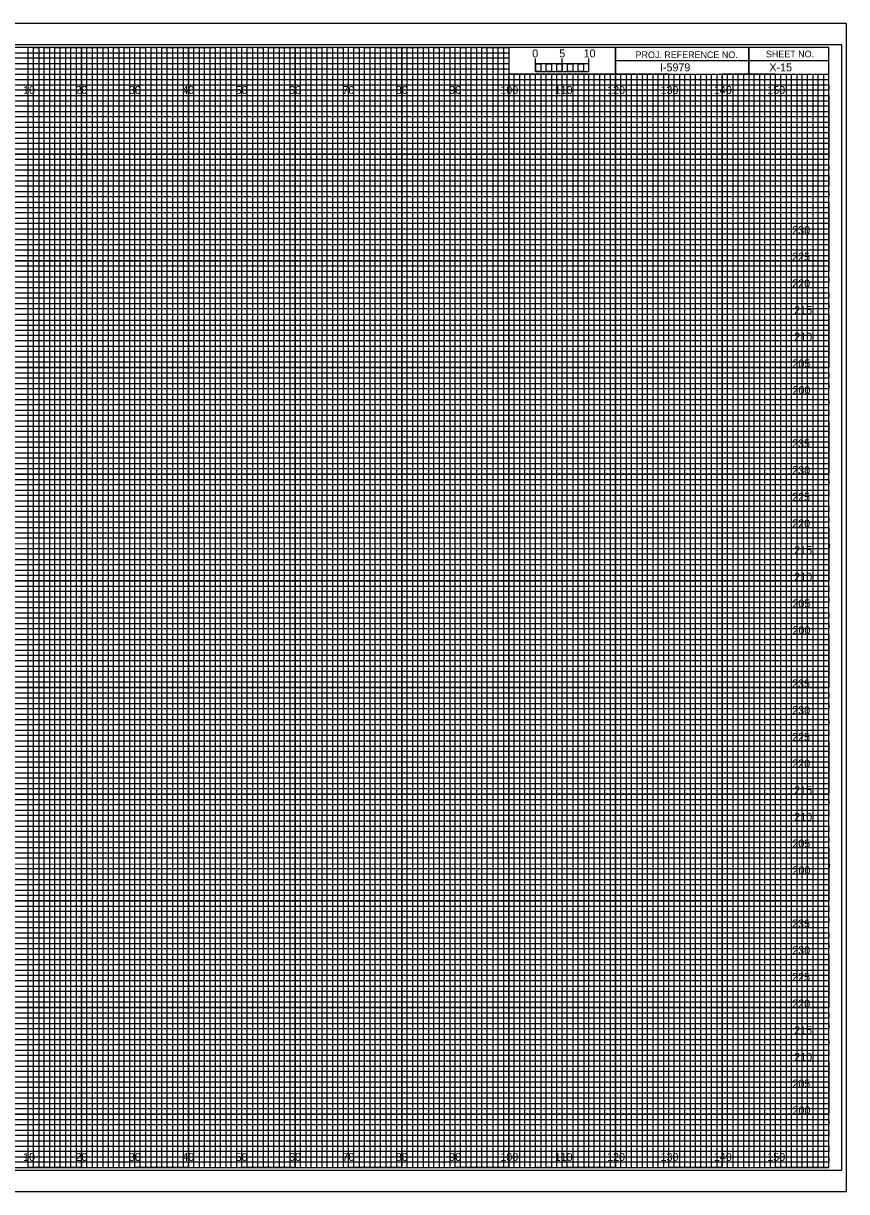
# Model space of a CAD drawing. Extents: x -13 to 323, y -5 to 654.
# Drawn here: x 169.1 to 323.3, y 215.5 to 434.5 of the extents above; entities that cross this region are included whole.
import ezdxf

# ---------------------------------------------------------------- set-up
doc = ezdxf.new("R2010")
doc.units = 0
for name, color, linetype in [('Prop XS Bar Scale Labels', 7, 'Continuous'), ('Prop XS Elevation Labels', 7, 'Continuous'), ('Prop XS Offset Labels', 7, 'Continuous'), ('Prop XS Project Number', 7, 'Continuous'), ('Prop XS Sheet Number', 7, 'Continuous'), ('Sheet Cross Section CELL', 7, 'Continuous'), ('Sheet Cross Section Grid Major CELL', 7, 'Continuous'), ('Sheet Cross Section Grid Middle CELL', 7, 'Continuous'), ('Sheet Cross Section Grid Minor 1 CELL', 7, 'Continuous'), ('Sheet Cross Section Grid Minor 2 CELL', 7, 'Continuous'), ('Sheet Cross Section Scale CELL', 7, 'Continuous'), ('Sheet Cutting Line CELL', 7, 'Continuous'), ('Sheet DOT Grid CELL', 7, 'Continuous'), ('Sheet Plot Border Inside CELL', 7, 'Continuous'), ('Sheet Plot Border Outside CELL', 7, 'Continuous')]:
    doc.layers.add(name, color=color, linetype=linetype)

msp = doc.modelspace()

# ---------------------------------------------------------------- linework, layer by layer
at = {"layer": 'Sheet Cross Section CELL'}
for p, q in [((305, 430), (305, 425)), ((305, 425), (305, 430)), ((280, 427.5), (280, 425)), ((320, 427.49), (280, 427.49)), ((280, 425), (320, 425))]:
    msp.add_line(p, q, dxfattribs=at)
for points in [[(320, 430), (0, 430), (0, 220), (320, 220)], [(280, 430), (260, 430), (260, 425.03), (280, 425.03)], [(320, 430), (280, 430), (280, 425), (320, 425)]]:
    msp.add_lwpolyline(points, close=True, dxfattribs=at)
at = {"layer": 'Sheet Cross Section Grid Major CELL'}
for p, q in [((170, 430), (160, 430)), ((170, 220), (170, 430)), ((190, 430), (180, 430)), ((180, 430), (180, 220)), ((190, 220), (190, 430)), ((210, 430), (200, 430)), ((200, 430), (200, 220)), ((210, 220), (210, 430)), ((230, 430), (220, 430)), ((220, 430), (220, 220)), ((230, 220), (230, 430)), ((250, 430), (240, 430)), ((240, 430), (240, 220)), ((250, 220), (250, 430)), ((260, 430), (260, 220)), ((270, 220), (270, 425)), ((290, 425), (280, 425)), ((280, 425), (280, 220)), ((290, 220), (290, 425)), ((310, 425), (300, 425)), ((300, 425), (300, 220)), ((310, 220), (310, 425)), ((180, 220), (170, 220)), ((200, 220), (190, 220)), ((220, 220), (210, 220)), ((240, 220), (230, 220)), ((260, 220), (250, 220)), ((280, 220), (270, 220)), ((300, 220), (290, 220)), ((320, 220), (310, 220)), ((320, 220), (320, 220))]:
    msp.add_line(p, q, dxfattribs=at)
for points in [[(0, 420), (320, 420), (320, 410), (0, 410)], [(0, 400), (320, 400), (320, 390), (0, 390)], [(0, 380), (320, 380), (320, 370), (0, 370)], [(0, 360), (320, 360), (320, 350), (0, 350)], [(0, 340), (320, 340), (320, 330), (0, 330)], [(0, 320), (320, 320), (320, 310), (0, 310)], [(0, 300), (320, 300), (320, 290), (0, 290)], [(0, 280), (320, 280), (320, 270), (0, 270)], [(0, 260), (320, 260), (320, 250), (0, 250)], [(0, 240), (320, 240), (320, 230), (0, 230)]]:
    msp.add_lwpolyline(points, dxfattribs=at)
at = {"layer": 'Sheet Cross Section Grid Middle CELL'}
for points in [[(165, 220), (175, 220), (175, 430), (185, 430), (185, 220), (195, 220), (195, 430), (205, 430), (205, 220), (215, 220), (215, 430), (225, 430), (225, 220), (235, 220), (235, 430), (245, 430), (245, 220), (255, 220), (255, 430), (259.93, 430), (260, 430), (260, 425), (264.99, 425), (264.99, 220), (275, 220), (275, 425), (285, 425), (285, 220), (295, 220), (295, 425), (305, 425), (305, 220), (315, 220), (315, 425)], [(0, 425), (275, 425)], [(0, 405), (320, 405), (320, 415), (0, 415)], [(0, 385), (320, 385), (320, 395), (0, 395)], [(0, 365), (320, 365), (320, 375), (0, 375)], [(0, 345), (320, 345), (320, 355), (0, 355)], [(0, 325), (320, 325), (320, 335), (0, 335)], [(0, 305), (320, 305), (320, 315), (0, 315)], [(0, 285), (320, 285), (320, 295), (0, 295)], [(0, 265), (320, 265), (320, 275), (0, 275)], [(0, 245), (320, 245), (320, 255), (0, 255)], [(0, 225), (320, 225), (320, 235), (0, 235)]]:
    msp.add_lwpolyline(points, dxfattribs=at)
at = {"layer": 'Sheet Cross Section Grid Minor 1 CELL'}
for p, q in [((0, 429), (260, 429)), ((260, 427.98), (0, 427.98)), ((260, 429), (260, 427.98)), ((0, 427), (260, 427)), ((260, 425.89), (0, 425.89)), ((260, 427), (260, 425.89)), ((0, 424), (320, 424))]:
    msp.add_line(p, q, dxfattribs=at)
for points in [[(0, 423), (270, 423), (320, 423), (320, 422), (0, 422)], [(0, 421), (320, 421), (320, 419), (0, 419)], [(0, 418), (320, 418), (320, 417), (0, 416.98)], [(0, 416), (320, 416), (320, 414), (0, 414)], [(0, 413), (320, 413), (320, 412), (0, 412)], [(0, 411), (320, 411), (320, 409), (0, 409)], [(0, 408), (320, 408), (320, 407), (0, 407)], [(0, 406), (320, 406), (320, 404), (0, 404)], [(0, 403), (320, 403), (320, 402), (0, 402)], [(0, 401), (320, 401), (320, 399), (0, 399)], [(0, 398), (320, 398), (320, 397), (0, 397)], [(0, 396), (320, 396), (320, 393.95), (320, 393), (320, 392), (0, 392)], [(0, 394), (320, 394), (320, 393), (0, 393)], [(0, 391), (320, 391), (320, 389), (0, 389.03)], [(0, 389.03), (320, 389), (320, 388), (0, 388)], [(0, 387), (320, 387), (320, 386), (0, 386)], [(0, 384), (320, 384), (320, 383), (0, 383)], [(0, 382), (320, 382), (320, 381), (0, 381)], [(-0.07, 378.89), (320, 378.89), (320, 377.88), (-0.07, 377.88)], [(0, 377), (320, 377), (320, 376), (0, 376)], [(0, 374), (320, 374), (320, 373), (0, 373)], [(0, 372), (320, 372), (320, 371), (0, 371)], [(0, 369), (320, 369), (320, 368), (0, 368)], [(0, 367), (320, 367), (320, 366), (0, 366)], [(0, 364), (320, 364), (320, 363), (0, 363)], [(0, 362), (320, 362), (320, 361), (0, 361)], [(0, 359), (320, 359), (319.99, 357.98), (0, 358)], [(0, 357), (320, 357), (320, 356), (0, 356)], [(0, 354), (320, 354), (320, 353), (0, 353)], [(0, 352), (320, 352), (320, 351), (0, 351)], [(0, 349), (320, 349), (320, 348), (0, 348)], [(0, 347), (320, 347), (320, 346), (0, 346)], [(0, 344), (320, 344), (320, 343), (0, 343)], [(0, 342), (320, 342), (320, 341), (0, 341)], [(0, 339), (320, 339), (320, 338), (0, 338)], [(0, 336.99), (320.07, 336.91), (320, 336), (0, 336)], [(0, 334), (320, 334), (320, 333), (0, 333)], [(0, 332), (320, 332), (320, 331), (0, 331)], [(0, 329), (320, 329), (320, 328), (0, 328)], [(0, 327), (320, 327), (320, 326), (0, 326)], [(0, 324), (320, 324), (320, 323), (0, 323)], [(0, 322), (320, 322), (320, 321), (0, 321)], [(0, 319), (320, 319), (320, 318), (0, 318)], [(0, 317), (320, 317), (320, 316), (0, 316)], [(0, 314), (320, 314), (320, 313), (0, 313)], [(0, 312), (320, 312), (320, 311), (0, 311)], [(0, 309), (320, 309), (320, 308), (0, 308)], [(0, 307), (320, 307), (320, 306), (0, 306)], [(0, 304), (320, 304), (320, 303), (0, 303)], [(0, 302), (320, 302), (320, 301), (0, 301)], [(0, 299), (320, 299), (319.99, 297.98), (0, 298)], [(0, 297), (320, 297), (320, 296), (0, 296)], [(0, 294), (320, 294), (320, 293), (0, 293)], [(0, 292), (320, 292), (320, 291), (0, 291)], [(0, 289), (320, 289), (320, 288), (0, 288)], [(0, 287), (320, 287), (320, 286), (0, 286)], [(0, 284), (320, 284), (320, 283), (0, 283)], [(0, 282), (320, 282), (320, 281), (0, 281)], [(0, 279), (320, 279), (320, 278), (0, 278)], [(0, 276.99), (320.07, 276.91), (320, 276), (0, 276)], [(0, 274), (320, 274), (320, 273), (0, 273)], [(0, 272), (320, 272), (320, 271), (0, 271)], [(0, 269), (320, 269), (320, 268), (0, 268)], [(0, 267), (320, 267), (320, 266), (0, 266)], [(0, 264), (320, 264), (320, 263), (0, 263)], [(0, 262), (320, 262), (320, 261), (0, 261)], [(0, 259), (320, 259), (320, 258), (0, 258)], [(0, 257), (320, 257), (320, 256), (0, 256)], [(0, 254), (320, 254), (320, 253), (0, 253)], [(0, 252), (320, 252), (320, 251), (0, 251)], [(0, 249), (320, 249), (320, 248), (0, 248)], [(0, 247), (320, 247), (320, 246), (0, 246)], [(0, 244), (320, 244), (320, 243), (0, 243)], [(0, 242), (320, 242), (320, 241), (0, 241)], [(0, 239), (320, 239), (320, 238), (0, 238)], [(0, 237), (320, 237), (320, 236), (0, 236)], [(0, 234), (320, 234), (320, 233), (0, 233)], [(0, 232), (320, 232), (320, 231), (0, 231)], [(0, 229), (320, 229), (320, 228), (0, 228)], [(0, 227), (320, 227), (320, 226), (0, 226)], [(0, 224), (320, 224), (320, 223), (0, 223)], [(0, 222), (320, 222), (320, 221), (0, 221)]]:
    msp.add_lwpolyline(points, dxfattribs=at)
at = {"layer": 'Sheet Cross Section Grid Minor 2 CELL'}
for p, q in [((267, 425), (266.01, 425)), ((266.01, 425), (266.01, 220)), ((267, 220), (267, 425)), ((269, 425), (268, 425)), ((268, 425), (268, 220)), ((269, 220), (269, 425)), ((266.01, 220), (265, 220)), ((268, 220), (267, 220))]:
    msp.add_line(p, q, dxfattribs=at)
for points in [[(170, 220), (171, 220), (171, 430), (172, 430), (172, 220)], [(172, 220), (173, 220), (173, 430), (174, 430), (174, 220)], [(175, 220), (176, 220), (176, 430), (177, 430), (177, 220)], [(177, 220), (178, 220), (178, 430), (179, 430), (179, 220)], [(180, 220), (181, 220), (181, 430), (182, 430), (182, 220)], [(182, 220), (183, 220), (183, 430), (184, 430), (184, 220)], [(185, 220), (186, 220), (186, 430), (187, 430), (187, 220)], [(187, 220), (188, 220), (188, 430), (189, 430), (189, 220)], [(190, 220), (191, 220), (191, 430), (192, 430), (192, 220)], [(192, 220), (193, 220), (193, 430), (194, 430), (194, 220)], [(195, 220), (196, 220), (196, 430), (197, 430), (197, 220)], [(197, 220), (198, 220), (198, 430), (199, 430), (199, 220)], [(200, 220), (201, 220), (201, 430), (202, 430), (202, 220)], [(202, 220), (203, 220), (203, 430), (204, 430), (204, 220)], [(205, 220), (206, 220), (206, 430), (207, 430), (207, 220)], [(207, 220), (208, 220), (208, 430), (209, 430), (209, 220)], [(210, 220), (211, 220), (211, 430), (212, 430), (212, 220)], [(212, 220), (213, 220), (213, 430), (214, 430), (214, 220)], [(215, 220), (216, 220), (216, 430), (217, 430), (217, 220)], [(217, 220), (218, 220), (218, 430), (219, 430), (219, 220)], [(220, 220), (221, 220), (221, 430), (222, 430), (222, 220)], [(222, 220), (223, 220), (223, 430), (224, 430), (224, 220)], [(225, 220), (226, 220), (226, 430), (227, 430), (227, 220)], [(227, 220), (228, 220), (228, 430), (229, 430), (229, 220)], [(230, 220), (231, 220), (231, 430), (232, 430), (232, 220)], [(232, 220), (233, 220), (233, 430), (234, 430), (234, 220)], [(235, 220), (236, 220), (236, 430), (237, 430), (237, 220)], [(237, 220), (238, 220), (238, 430), (239, 430), (239, 220)], [(240, 220), (241, 220), (241, 430), (242, 430), (242, 220)], [(242, 220), (243, 220), (243, 430), (244, 430), (244, 220)], [(245, 220), (246, 220), (246, 430), (247, 430), (247, 220)], [(247, 220), (248, 220), (248, 430), (249, 430), (249, 220)], [(250, 220), (251, 220), (251, 430), (252, 430), (252, 220)], [(252, 220), (253, 220), (253, 430), (254, 430), (254, 220)], [(255, 220), (256, 220), (256, 430), (257, 430), (257, 220)], [(257, 220), (258, 220), (258, 430), (259, 430), (259, 220)], [(260, 220), (261, 220), (261, 425), (262.02, 425), (262.02, 220)], [(262, 220), (263, 220), (263, 425), (263.99, 425), (263.99, 220)], [(270, 220), (270.98, 220), (270.98, 425), (272, 425), (272, 220)], [(272, 220), (273, 220), (273, 425), (274.05, 425), (274.05, 220)], [(275, 220), (276, 220), (276, 425), (277, 425), (277, 220)], [(277, 220), (278, 220), (278, 425), (279, 425), (279, 220)], [(280, 220), (281, 220), (281, 425), (282, 425), (282, 220)], [(282, 220), (283, 220), (283, 425), (284, 425), (284, 220)], [(285, 220), (286, 220), (286, 425), (287, 425), (287, 220)], [(287, 220), (288, 220), (288, 425), (289, 425), (289, 220)], [(290, 220), (291, 220), (291, 425), (292, 425), (292, 220)], [(292, 220), (293, 220), (293, 425), (294, 425), (294, 220)], [(295, 220), (296, 220), (296, 425), (297, 425), (297, 220)], [(297, 220), (298, 220), (298, 425), (299, 425), (299, 220)], [(300, 220), (301, 220), (301, 425), (302, 425), (302, 220)], [(302, 220), (303, 220), (303, 425), (304, 425), (304, 220)], [(305, 220), (306, 220), (306, 425), (307, 425), (307, 220)], [(307, 220), (308, 220), (308, 425), (309, 425), (309, 220)], [(310, 220), (311, 220), (311, 425), (312, 425), (312, 220)], [(312, 220), (313, 220), (313, 425), (314, 425), (314, 220)], [(315, 220), (316, 220), (316, 425), (317, 425), (317, 220)], [(317, 220), (318, 220), (318, 425), (319, 425), (319, 220)]]:
    msp.add_lwpolyline(points, dxfattribs=at)
at = {"layer": 'Sheet Cross Section Scale CELL'}
for p, q in [((265, 425.49), (265, 427.9)), ((265, 426.9), (265, 427.9)), ((270, 425.49), (270, 427.9)), ((275, 425.49), (275, 427.9)), ((275, 426.9), (275, 427.9))]:
    msp.add_line(p, q, dxfattribs=at)
for points in [[(275, 426.9), (265, 426.9), (265, 425.49), (275, 425.49)], [(265, 426.9), (266, 426.9), (266, 425.49), (265, 425.49)], [(267, 426.9), (268, 426.9), (268, 425.49), (267, 425.49)], [(269, 426.9), (270, 426.9), (270, 425.49), (269, 425.49)], [(271, 426.9), (272, 426.9), (272, 425.49), (271, 425.49)], [(273, 426.9), (274, 426.9), (274, 425.49), (273, 425.49)]]:
    msp.add_lwpolyline(points, close=True, dxfattribs=at)
at = {"layer": 'Sheet Cutting Line CELL'}
for p, q in [((323.3, 434.5), (-13.4, 434.5)), ((-13.4, 215.5), (323.3, 215.5))]:
    msp.add_line(p, q, dxfattribs=at)
at = {"layer": 'Sheet DOT Grid CELL'}
for p, q in [((170, 220), (170, 430)), ((180, 220), (180, 430)), ((190, 220), (190, 430)), ((200, 220), (200, 430)), ((210, 220), (210, 430)), ((220, 220), (220, 430)), ((230, 220), (230, 430)), ((240, 220), (240, 430)), ((250, 220), (250, 430)), ((260, 220), (260, 424.69)), ((270, 220), (270, 424.69)), ((280, 220), (280, 424.69)), ((290, 220), (290, 424.69)), ((300, 220), (300, 424.69)), ((310, 220), (310, 424.69)), ((0, 420), (320, 420)), ((0, 410), (320, 410)), ((0, 400), (320, 400)), ((0, 390), (320, 390)), ((0, 380), (320, 380)), ((0, 370), (320, 370)), ((0, 360), (320, 360)), ((0, 350), (320, 350)), ((0, 340), (320, 340)), ((0, 330), (320, 330)), ((0, 320), (320, 320)), ((0, 310), (320, 310)), ((0, 300), (320, 300)), ((0, 290), (320, 290)), ((0, 280), (320, 280)), ((0, 270), (320, 270)), ((0, 260), (320, 260)), ((0, 250), (320, 250)), ((0, 240), (320, 240)), ((0, 230), (320, 230))]:
    msp.add_line(p, q, dxfattribs=at)
at = {"layer": 'Sheet Plot Border Inside CELL'}
msp.add_lwpolyline([(-10.8, 219.5), (322.4, 219.5), (322.4, 430.5), (-10.8, 430.5)], close=True, dxfattribs=at)
at = {"layer": 'Sheet Plot Border Outside CELL'}
msp.add_lwpolyline([(-13.4, 215.5), (323.3, 215.5), (323.3, 434.5), (-13.4, 434.5)], close=True, dxfattribs=at)

# ---------------------------------------------------------------- texts
at = {"layer": 'Prop XS Bar Scale Labels'}
for s, p in [('5', (269.47, 428.12)), ('10', (274.04, 428.12))]:
    msp.add_text(s, height=1.5, dxfattribs=at).set_placement(p)
at = {"layer": 'Prop XS Elevation Labels'}
for s, p in [('230', (313.11, 395)), ('225', (313.1, 390)), ('220', (313.12, 385)), ('215', (313.48, 380)), ('210', (313.5, 375)), ('205', (313.15, 370)), ('200', (313.17, 365)), ('235', (313.09, 355)), ('230', (313.11, 350)), ('225', (313.1, 345)), ('220', (313.12, 340)), ('215', (313.48, 335)), ('210', (313.5, 330)), ('205', (313.15, 325)), ('200', (313.17, 320)), ('235', (313.09, 310)), ('230', (313.11, 305)), ('225', (313.1, 300)), ('220', (313.12, 295)), ('215', (313.48, 290)), ('210', (313.5, 285)), ('205', (313.15, 280)), ('200', (313.17, 275)), ('235', (313.09, 265)), ('230', (313.11, 260)), ('225', (313.1, 255)), ('220', (313.12, 250)), ('215', (313.48, 245)), ('210', (313.5, 240)), ('205', (313.15, 235)), ('200', (313.17, 230))]:
    msp.add_text(s, height=1.5, dxfattribs=at).set_placement(p)
at = {"layer": 'Prop XS Offset Labels'}
for s, p in [('10', (169.04, 421.25)), ('20', (178.86, 421.25)), ('30', (188.86, 421.25)), ('40', (198.86, 421.25)), ('50', (208.86, 421.25)), ('60', (218.86, 421.25)), ('70', (228.86, 421.25)), ('80', (238.86, 421.25)), ('90', (248.86, 421.25)), ('100', (258.44, 421.25)), ('110', (268.62, 421.25)), ('120', (278.44, 421.25)), ('130', (288.44, 421.25)), ('140', (298.44, 421.25)), ('150', (308.44, 421.25)), ('10', (169.04, 221.25)), ('20', (178.86, 221.25)), ('30', (188.86, 221.25)), ('40', (198.86, 221.25)), ('50', (208.86, 221.25)), ('60', (218.86, 221.25)), ('70', (228.86, 221.25)), ('80', (238.86, 221.25)), ('90', (248.86, 221.25)), ('100', (258.44, 221.25)), ('110', (268.62, 221.25)), ('120', (278.44, 221.25)), ('130', (288.44, 221.25)), ('140', (298.44, 221.25)), ('150', (308.44, 221.25))]:
    msp.add_text(s, height=1.5, dxfattribs=at).set_placement(p)
at = {"layer": 'Prop XS Project Number'}
msp.add_text('I-5979', height=1.5, dxfattribs=at).set_placement((288.34, 425.5))
at = {"layer": 'Prop XS Sheet Number'}
msp.add_text('X-15', height=1.5, dxfattribs=at).set_placement((308.83, 425.5))
at = {"layer": 'Sheet Cross Section CELL'}
for s, p in [('PROJ. REFERENCE NO.', (283.77, 427.99)), ('SHEET NO.', (308.19, 428.12))]:
    msp.add_text(s, height=1.25, dxfattribs=at).set_placement(p)
at = {"layer": 'Sheet Cross Section Scale CELL'}
msp.add_text('0', height=1.5, dxfattribs=at).set_placement((264.41, 428.12))

doc.saveas('drawing.dxf')
